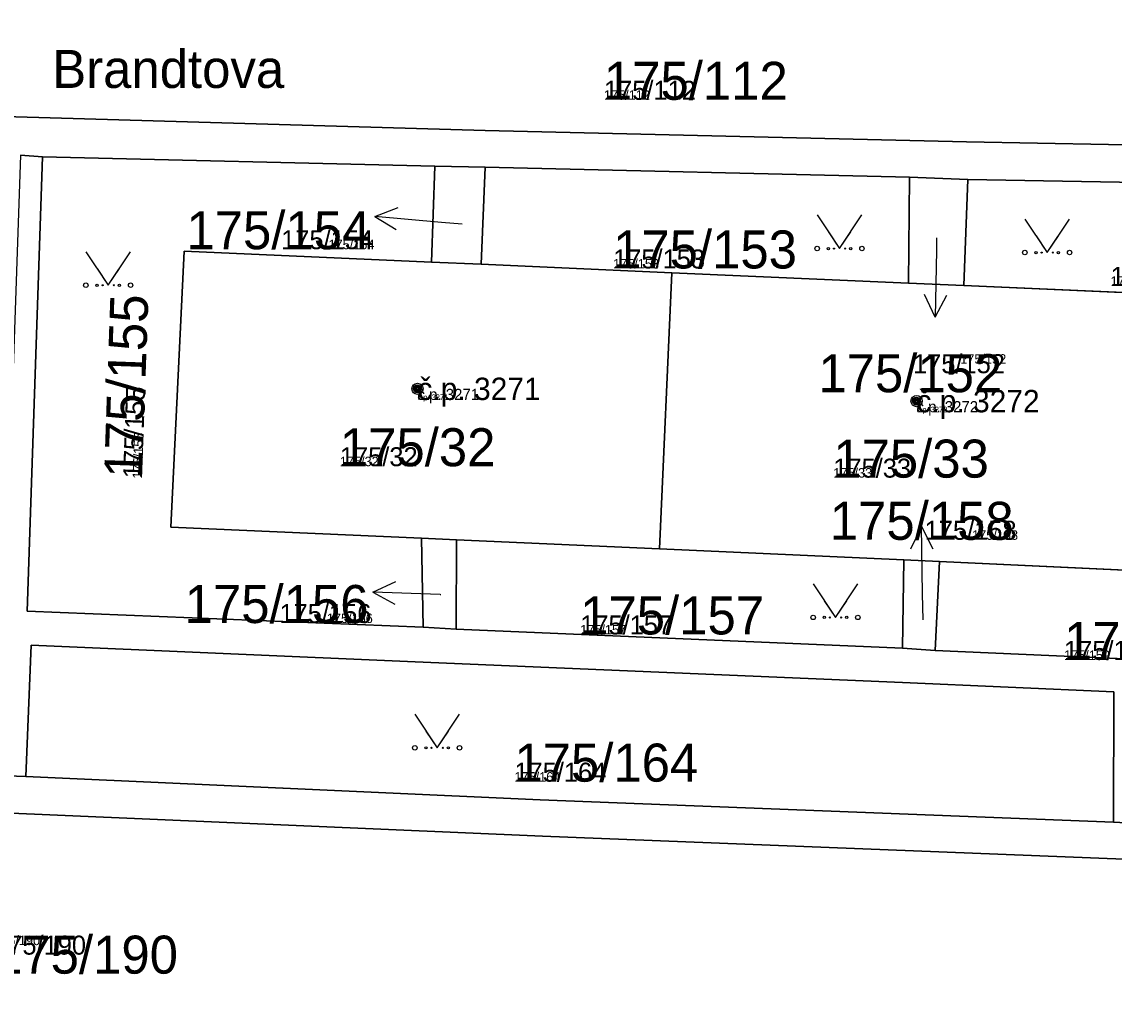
# Model space of a CAD drawing. Extents: x -759873 to -758487, y -975024 to -973516.
# Drawn here: x -759554.93 to -759506.12, y -974653.71 to -974610.24 of the extents above; entities that cross this region are included whole.
import ezdxf

# ---------------------------------------------------------------- set-up
doc = ezdxf.new("R2010")
doc.units = 0
for name, color, linetype in [('KAT_02_hranice parcel', 7, 'Continuous'), ('KAT_03_1000_st čísla parcelní', 7, 'Continuous'), ('KAT_03_1000_čísla parcelní', 7, 'Continuous'), ('KAT_03_1000_čísla popisná', 7, 'Continuous'), ('KAT_03_250_st čísla parcelní', 7, 'Continuous'), ('KAT_03_250_čísla parcelní', 7, 'Continuous'), ('KAT_03_250_čísla popisná', 7, 'Continuous'), ('KAT_03_500_st čísla parcelní', 7, 'Continuous'), ('KAT_03_500_čísla parcelní', 7, 'Continuous'), ('KAT_03_500_čísla popisná', 7, 'Continuous'), ('KAT_05_1000_značky kultur', 7, 'Continuous'), ('KAT_05_250_značky kultur', 7, 'Continuous'), ('KAT_05_500_značky kultur', 7, 'Continuous'), ('KAT_07_1000_značky budov', 7, 'Continuous'), ('KAT_07_250_značky budov', 7, 'Continuous'), ('KAT_07_500_značky budov', 7, 'Continuous'), ('KAT_12_pomocná šipka', 7, 'Continuous'), ('KAT_13_popis', 7, 'Continuous'), ('KAT_14_plocha_budovy', 7, 'Continuous'), ('KAT_14_plocha_pozemek', 7, 'Continuous')]:
    doc.layers.add(name, color=color, linetype=linetype)

msp = doc.modelspace()

# ---------------------------------------------------------------- linework, layer by layer
at = {"layer": 'KAT_02_hranice parcel'}
for p, q in [((-759554.99, -974616.21), (-759554, -974616.28)), ((-759554, -974616.28), (-759536.47, -974616.69)), ((-759536.47, -974616.69), (-759536.62, -974620.99)), ((-759536.47, -974616.69), (-759534.22, -974616.74)), ((-759534.22, -974616.74), (-759534.41, -974621.08)), ((-759534.22, -974616.74), (-759515.27, -974617.19)), ((-759515.27, -974617.19), (-759515.31, -974621.93)), ((-759515.27, -974617.19), (-759512.66, -974617.3)), ((-759512.66, -974617.3), (-759512.84, -974622.03)), ((-759512.66, -974617.3), (-759493.18, -974617.63)), ((-759534.41, -974621.08), (-759536.62, -974620.99)), ((-759525.88, -974621.46), (-759534.41, -974621.08)), ((-759526.43, -974633.8), (-759525.88, -974621.46)), ((-759515.31, -974621.93), (-759525.88, -974621.46)), ((-759512.84, -974622.03), (-759515.31, -974621.93)), ((-759504.08, -974622.42), (-759512.84, -974622.03)), ((-759537.07, -974633.33), (-759535.51, -974633.4)), ((-759537, -974637.31), (-759537.07, -974633.33)), ((-759535.52, -974637.39), (-759535.51, -974633.4)), ((-759535.51, -974633.4), (-759526.43, -974633.8)), ((-759526.43, -974633.8), (-759515.51, -974634.3)), ((-759515.58, -974638.24), (-759515.51, -974634.3)), ((-759515.51, -974634.3), (-759513.93, -974634.37)), ((-759514.11, -974638.35), (-759513.93, -974634.37)), ((-759513.93, -974634.37), (-759504.66, -974634.8)), ((-759535.52, -974637.39), (-759537, -974637.31)), ((-759515.58, -974638.24), (-759535.52, -974637.39)), ((-759514.11, -974638.35), (-759515.58, -974638.24)), ((-759493.45, -974639.25), (-759514.11, -974638.35)), ((-759556.4, -974643.92), (-759554.75, -974643.98)), ((-759506.15, -974646.02), (-759504.71, -974646.1))]:
    msp.add_line(p, q, dxfattribs=at)
for points in [[(-759748.01, -974589.58), (-759742.78, -974592.68), (-759732.01, -974598.91), (-759728.99, -974600.68), (-759725.4, -974602.45), (-759718.02, -974604.75), (-759709.84, -974606.71), (-759702.63, -974608.03), (-759689.82, -974608.95), (-759677.23, -974609.87), (-759664.06, -974610.49), (-759641.64, -974611.43), (-759620.48, -974612.36), (-759598.5, -974613.15), (-759577.03, -974613.93), (-759558.28, -974614.4), (-759534.22, -974615.1), (-759512.72, -974615.61), (-759490.5, -974616.02), (-759471.82, -974616.25), (-759458.92, -974616), (-759446.09, -974615.46)], [(-759537, -974637.31), (-759554.69, -974636.59), (-759554, -974616.28)], [(-759536.62, -974620.99), (-759547.68, -974620.5), (-759548.27, -974632.83), (-759537.07, -974633.33)], [(-759554.75, -974643.98), (-759554.51, -974638.11), (-759537.36, -974638.86), (-759515.58, -974639.78), (-759506.13, -974640.2), (-759506.15, -974646.02)], [(-759554.75, -974643.98), (-759531.77, -974645.02), (-759506.15, -974646.02)], [(-759301.4, -974651.09), (-759309.93, -974650.8), (-759309.98, -974645.76), (-759323.06, -974645.78), (-759353.1, -974645.55), (-759386.38, -974645.33), (-759400.57, -974645.67), (-759414.93, -974646.26), (-759414.73, -974651.33), (-759436.14, -974652.5), (-759441.93, -974652.85), (-759450.38, -974653.47), (-759468.91, -974653.71), (-759482.38, -974653.4), (-759482.33, -974648.6), (-759512.45, -974647.4), (-759531.67, -974646.64), (-759556.45, -974645.57)]]:
    msp.add_lwpolyline(points, dxfattribs=at)
at = {"layer": 'KAT_03_1000_čísla popisná'}
for centre in [(-759537.25, -974626.65), (-759514.95, -974627.2)]:
    msp.add_circle(centre, 0.25, dxfattribs=at)
at = {"layer": 'KAT_03_250_čísla popisná'}
for centre in [(-759537.25, -974626.65), (-759514.95, -974627.2)]:
    msp.add_circle(centre, 0.0625, dxfattribs=at)
at = {"layer": 'KAT_03_500_čísla popisná'}
for centre in [(-759537.25, -974626.65), (-759514.95, -974627.2)]:
    msp.add_circle(centre, 0.125, dxfattribs=at)
at = {"layer": 'KAT_05_1000_značky kultur'}
for points in [[(-759519.39, -974618.879), (-759518.39, -974620.38), (-759517.39, -974618.879)], [(-759510.11, -974619.059), (-759509.11, -974620.56), (-759508.11, -974619.059)], [(-759552.07, -974620.519), (-759551.07, -974622.02), (-759550.07, -974620.519)], [(-759519.57, -974635.369), (-759518.57, -974636.87), (-759517.57, -974635.369)], [(-759537.37, -974641.199), (-759536.37, -974642.7), (-759535.37, -974641.199)]]:
    msp.add_lwpolyline(points, dxfattribs=at)
for centre in [(-759519.39, -974620.379), (-759517.39, -974620.379), (-759510.11, -974620.559), (-759508.11, -974620.559), (-759552.07, -974622.019), (-759550.07, -974622.019), (-759519.57, -974636.869), (-759517.57, -974636.869), (-759537.37, -974642.699), (-759535.37, -974642.699)]:
    msp.add_circle(centre, 0.1, dxfattribs=at)
at = {"layer": 'KAT_05_250_značky kultur'}
for points in [[(-759518.64, -974620.005), (-759518.39, -974620.38), (-759518.14, -974620.005)], [(-759509.36, -974620.185), (-759509.11, -974620.56), (-759508.86, -974620.185)], [(-759551.32, -974621.645), (-759551.07, -974622.02), (-759550.82, -974621.645)], [(-759518.82, -974636.495), (-759518.57, -974636.87), (-759518.32, -974636.495)], [(-759536.62, -974642.325), (-759536.37, -974642.7), (-759536.12, -974642.325)]]:
    msp.add_lwpolyline(points, dxfattribs=at)
for centre in [(-759518.64, -974620.38), (-759518.14, -974620.38), (-759509.36, -974620.56), (-759508.86, -974620.56), (-759551.32, -974622.02), (-759550.82, -974622.02), (-759518.82, -974636.87), (-759518.32, -974636.87), (-759536.62, -974642.7), (-759536.12, -974642.7)]:
    msp.add_circle(centre, 0.025, dxfattribs=at)
at = {"layer": 'KAT_05_500_značky kultur'}
for points in [[(-759518.89, -974619.63), (-759518.39, -974620.38), (-759517.89, -974619.63)], [(-759509.61, -974619.809), (-759509.11, -974620.56), (-759508.61, -974619.809)], [(-759551.57, -974621.27), (-759551.07, -974622.02), (-759550.57, -974621.27)], [(-759519.07, -974636.12), (-759518.57, -974636.87), (-759518.07, -974636.12)], [(-759536.87, -974641.949), (-759536.37, -974642.7), (-759535.87, -974641.949)]]:
    msp.add_lwpolyline(points, dxfattribs=at)
for centre in [(-759518.89, -974620.38), (-759517.89, -974620.38), (-759509.61, -974620.56), (-759508.61, -974620.56), (-759551.57, -974622.02), (-759550.57, -974622.02), (-759519.07, -974636.87), (-759518.07, -974636.87), (-759536.87, -974642.7), (-759535.87, -974642.7)]:
    msp.add_circle(centre, 0.05, dxfattribs=at)
at = {"layer": 'KAT_07_1000_značky budov'}
for centre in [(-759537.257, -974626.649), (-759514.957, -974627.199)]:
    msp.add_circle(centre, 0.175, dxfattribs=at)
at = {"layer": 'KAT_07_250_značky budov'}
for centre in [(-759537.252, -974626.65), (-759514.952, -974627.2)]:
    msp.add_circle(centre, 0.0437, dxfattribs=at)
at = {"layer": 'KAT_07_500_značky budov'}
for centre in [(-759537.253, -974626.65), (-759514.953, -974627.2)]:
    msp.add_circle(centre, 0.0875, dxfattribs=at)
at = {"layer": 'KAT_12_pomocná šipka'}
for p, q in [((-759539.16, -974618.948), (-759538.118, -974618.537)), ((-759536.17, -974619.21), (-759539.16, -974618.948)), ((-759539.16, -974618.948), (-759538.206, -974619.535)), ((-759535.26, -974619.29), (-759536.17, -974619.21)), ((-759514.05, -974619.9), (-759514.06, -974620.45)), ((-759514.06, -974620.45), (-759514.112, -974623.451)), ((-759514.112, -974623.451), (-759514.596, -974622.44)), ((-759514.112, -974623.451), (-759513.594, -974622.458)), ((-759514.732, -974632.809), (-759515.216, -974633.82)), ((-759514.68, -974635.81), (-759514.732, -974632.809)), ((-759514.732, -974632.809), (-759514.214, -974633.802)), ((-759539.239, -974635.735), (-759538.221, -974635.27)), ((-759536.24, -974635.84), (-759539.239, -974635.735)), ((-759539.239, -974635.735), (-759538.256, -974636.271)), ((-759536.24, -974635.84), (-759536.21, -974635.84)), ((-759514.65, -974636.97), (-759514.68, -974635.81))]:
    msp.add_line(p, q, dxfattribs=at)
at = {"layer": 'KAT_14_plocha_budovy'}
for points in [[(-759548.27, -974632.83), (-759537.07, -974633.33), (-759535.51, -974633.4), (-759526.43, -974633.8), (-759525.88, -974621.46), (-759534.41, -974621.08), (-759536.62, -974620.99), (-759547.68, -974620.5)], [(-759504.66, -974634.8), (-759504.08, -974622.42), (-759512.84, -974622.03), (-759515.31, -974621.93), (-759525.88, -974621.46), (-759526.43, -974633.8), (-759515.51, -974634.3), (-759513.93, -974634.37)]]:
    msp.add_lwpolyline(points, close=True, dxfattribs=at)
at = {"layer": 'KAT_14_plocha_pozemek'}
for points in [[(-759446.09, -974615.46), (-759458.92, -974616), (-759471.82, -974616.25), (-759490.5, -974616.02), (-759512.72, -974615.61), (-759534.22, -974615.1), (-759558.28, -974614.4), (-759577.03, -974613.93), (-759598.5, -974613.15), (-759620.48, -974612.36)], [(-759620.48, -974612.36), (-759598.5, -974613.15), (-759577.03, -974613.93), (-759558.28, -974614.4), (-759534.22, -974615.1), (-759512.72, -974615.61), (-759490.5, -974616.02), (-759471.82, -974616.25), (-759458.92, -974616), (-759446.09, -974615.46)], [(-759453.76, -974638.72), (-759465.53, -974640.52), (-759470.44, -974640.27), (-759471.91, -974640.21), (-759491.95, -974639.29), (-759493.45, -974639.25), (-759514.11, -974638.35), (-759515.58, -974638.24), (-759535.52, -974637.39), (-759537, -974637.31), (-759554.69, -974636.59), (-759554, -974616.28), (-759554.99, -974616.21), (-759555.69, -974636.55), (-759578.04, -974635.54), (-759579.84, -974635.44), (-759599.58, -974634.68), (-759601.39, -974634.57), (-759621.66, -974633.76)], [(-759554.99, -974616.21), (-759554, -974616.28), (-759536.47, -974616.69), (-759534.22, -974616.74), (-759515.27, -974617.19), (-759512.66, -974617.3), (-759493.18, -974617.63), (-759490.52, -974617.67), (-759471.78, -974617.89), (-759469.17, -974617.92), (-759458.75, -974617.66), (-759453.56, -974617.5)], [(-759608.73, -974635.83), (-759601.54, -974636.08), (-759585.21, -974636.67), (-759576.31, -974637.16), (-759576.61, -974642.92), (-759575.19, -974642.84), (-759574.86, -974637.22), (-759556.11, -974638.04), (-759556.4, -974643.92), (-759554.75, -974643.98), (-759554.51, -974638.11), (-759537.36, -974638.86), (-759515.58, -974639.78), (-759506.13, -974640.2), (-759506.15, -974646.02), (-759504.71, -974646.1), (-759504.3, -974640.26), (-759492.11, -974640.81), (-759471.99, -974641.69), (-759465.33, -974642.08), (-759453.67, -974640.38)], [(-759450.38, -974653.47), (-759468.91, -974653.71), (-759482.38, -974653.4), (-759482.33, -974648.6), (-759512.45, -974647.4), (-759531.67, -974646.64), (-759556.45, -974645.57), (-759559.25, -974645.05), (-759559.6, -974650.39), (-759571.57, -974649.69), (-759577.12, -974649.37), (-759576.85, -974644.52), (-759594.91, -974643.96), (-759630.55, -974642.48)], [(-759455.76, -974651.64), (-759457.23, -974651.73), (-759469.03, -974651.9), (-759480.7, -974651.84), (-759480.58, -974647.06), (-759504.71, -974646.1), (-759506.15, -974646.02), (-759531.77, -974645.02), (-759554.75, -974643.98), (-759556.4, -974643.92), (-759556.45, -974645.57), (-759531.67, -974646.64), (-759512.45, -974647.4), (-759482.33, -974648.6), (-759482.38, -974653.4), (-759468.91, -974653.71), (-759450.38, -974653.47)]]:
    msp.add_lwpolyline(points, dxfattribs=at)
for points in [[(-759537, -974637.31), (-759537.07, -974633.33), (-759548.27, -974632.83), (-759547.68, -974620.5), (-759536.62, -974620.99), (-759536.47, -974616.69), (-759554, -974616.28), (-759554.69, -974636.59)], [(-759536.47, -974616.69), (-759536.62, -974620.99), (-759534.41, -974621.08), (-759534.22, -974616.74)], [(-759534.22, -974616.74), (-759534.41, -974621.08), (-759525.88, -974621.46), (-759515.31, -974621.93), (-759515.27, -974617.19)], [(-759515.27, -974617.19), (-759515.31, -974621.93), (-759512.84, -974622.03), (-759512.66, -974617.3)], [(-759512.66, -974617.3), (-759512.84, -974622.03), (-759504.08, -974622.42), (-759493.3, -974622.9), (-759493.18, -974617.63)], [(-759547.68, -974620.5), (-759548.27, -974632.83), (-759537.07, -974633.33), (-759535.51, -974633.4), (-759526.43, -974633.8), (-759525.88, -974621.46), (-759534.41, -974621.08), (-759536.62, -974620.99)], [(-759512.84, -974622.03), (-759515.31, -974621.93), (-759525.88, -974621.46), (-759526.43, -974633.8), (-759515.51, -974634.3), (-759513.93, -974634.37), (-759504.66, -974634.8), (-759504.08, -974622.42)], [(-759535.51, -974633.4), (-759537.07, -974633.33), (-759537, -974637.31), (-759535.52, -974637.39)], [(-759515.51, -974634.3), (-759526.43, -974633.8), (-759535.51, -974633.4), (-759535.52, -974637.39), (-759515.58, -974638.24)], [(-759513.93, -974634.37), (-759515.51, -974634.3), (-759515.58, -974638.24), (-759514.11, -974638.35)], [(-759493.45, -974639.25), (-759493.46, -974635.28), (-759504.66, -974634.8), (-759513.93, -974634.37), (-759514.11, -974638.35)], [(-759531.77, -974645.02), (-759506.15, -974646.02), (-759506.13, -974640.2), (-759515.58, -974639.78), (-759537.36, -974638.86), (-759554.51, -974638.11), (-759554.75, -974643.98)]]:
    msp.add_lwpolyline(points, close=True, dxfattribs=at)

# ---------------------------------------------------------------- texts
at = {"layer": 'KAT_03_1000_st čísla parcelní'}
for s, p in [('175/32', (-759540.72, -974630.11)), ('175/33', (-759518.67, -974630.62))]:
    msp.add_text(s, height=1.7, dxfattribs=at).set_placement(p)
at = {"layer": 'KAT_03_1000_čísla parcelní'}
for s, p in [('175/112', (-759528.92, -974613.73)), ('175/154', (-759547.576, -974620.41)), ('175/153', (-759528.51, -974621.27)), ('175/152', (-759519.336, -974626.803)), ('175/158', (-759518.826, -974633.4)), ('175/156', (-759547.656, -974637.12)), ('175/157', (-759529.98, -974637.63)), ('175/159', (-759508.36, -974638.77)), ('175/164', (-759532.92, -974644.21)), ('175/190', (-759556.17, -974652.793))]:
    msp.add_text(s, height=1.7, dxfattribs=at).set_placement(p)
msp.add_text('175/155', height=1.7, rotation=88, dxfattribs=at).set_placement((-759549.56, -974630.669))
at = {"layer": 'KAT_03_1000_čísla popisná'}
for s, p in [('č.p. 3271', (-759537.25, -974627.15)), ('č.p. 3272', (-759514.95, -974627.7))]:
    msp.add_text(s, height=1, dxfattribs=at).set_placement(p)
at = {"layer": 'KAT_03_250_st čísla parcelní'}
for s, p in [('175/32', (-759540.72, -974630.11)), ('175/33', (-759518.67, -974630.62))]:
    msp.add_text(s, height=0.425, dxfattribs=at).set_placement(p)
at = {"layer": 'KAT_03_250_čísla parcelní'}
for s, p in [('175/112', (-759528.92, -974613.73)), ('175/154', (-759541.226, -974620.41)), ('175/153', (-759528.51, -974621.27)), ('175/151', (-759506.28, -974622.049)), ('175/152', (-759512.994, -974625.528)), ('175/158', (-759512.468, -974633.4)), ('175/156', (-759541.3, -974637.12)), ('175/157', (-759529.98, -974637.63)), ('175/159', (-759508.36, -974638.77)), ('175/164', (-759532.92, -974644.21)), ('175/190', (-759556.17, -974651.518))]:
    msp.add_text(s, height=0.425, dxfattribs=at).set_placement(p)
msp.add_text('175/155', height=0.425, rotation=88, dxfattribs=at).set_placement((-759549.56, -974630.669))
at = {"layer": 'KAT_03_250_čísla popisná'}
for s, p in [('č.p. 3271', (-759537.25, -974627.15)), ('č.p. 3272', (-759514.95, -974627.7))]:
    msp.add_text(s, height=0.25, dxfattribs=at).set_placement(p)
at = {"layer": 'KAT_03_500_st čísla parcelní'}
for s, p in [('175/32', (-759540.72, -974630.11)), ('175/33', (-759518.67, -974630.62))]:
    msp.add_text(s, height=0.85, dxfattribs=at).set_placement(p)
at = {"layer": 'KAT_03_500_čísla parcelní'}
for s, p in [('175/112', (-759528.92, -974613.73)), ('175/154', (-759543.343, -974620.41)), ('175/153', (-759528.51, -974621.27)), ('175/151', (-759506.28, -974622.049)), ('175/152', (-759515.108, -974625.953)), ('175/158', (-759514.588, -974633.4)), ('175/156', (-759543.419, -974637.12)), ('175/157', (-759529.98, -974637.63)), ('175/159', (-759508.36, -974638.77)), ('175/164', (-759532.92, -974644.21)), ('175/190', (-759556.17, -974651.943))]:
    msp.add_text(s, height=0.85, dxfattribs=at).set_placement(p)
msp.add_text('175/155', height=0.85, rotation=88, dxfattribs=at).set_placement((-759549.56, -974630.669))
at = {"layer": 'KAT_03_500_čísla popisná'}
for s, p in [('č.p. 3271', (-759537.25, -974627.15)), ('č.p. 3272', (-759514.95, -974627.7))]:
    msp.add_text(s, height=0.5, dxfattribs=at).set_placement(p)
at = {"layer": 'KAT_13_popis'}
msp.add_text('Brandtova', height=1.7, dxfattribs=at).set_placement((-759553.57, -974613.2))

doc.saveas('drawing.dxf')
